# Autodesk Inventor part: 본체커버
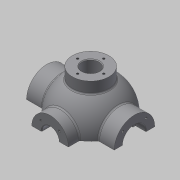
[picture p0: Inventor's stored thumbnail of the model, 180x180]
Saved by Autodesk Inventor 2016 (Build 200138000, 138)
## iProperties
Created: 2015-12
Part Number: 본체커버
Material: 일반
Document SubType Name: Modeling
Designer: mduedu
Density: 1 g/cm^3
Mass: 211.839 g
Surface Area: 451.737 cm^2
Volume: 211.839 cm^3
Appearance: 기본값
Author: mduedu
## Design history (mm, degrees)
sketch "스케치1"
  geometry: L1 (-53, 0)-(53, 0); A1 r 53 centre (0, 0) between (53, 0) and (-53, 0); 2 further points
  constraints: 2 coincident, 2 end point, 2 point on circle, 1 centre point, 1 horizontal, 1 midpoint
  dimensions: "d0" = 53 radius of A1
revolve "회전1" sketch "스케치1" stored, may be unused: angle "d2" = 90 deg
feature "쉘1" dims "d11" = 10
node "작업 평면1"
sketch "스케치2"
  geometry: C1 r 31 at (0, 0); 1 further point
  constraints: 1 centre point, 1 coincident
  dimensions: "d4" = 62 diameter of C1
extrude "돌출1" join sketch "스케치2" stored distance "d5" = 10; taper "d6" = 0 deg
node "작업 평면2"
sketch "스케치3"
  geometry: C1 r 28 at (0, 0); 1 further point
  constraints: 1 centre point, 1 coincident
  dimensions: "d8" = 56 diameter of C1
extrude "돌출2" join sketch "스케치3" stored distance "d9" = 10; taper "d10" = 0 deg
hole "구멍1" diameter "d14" = 35; stored, may be unused: countersink angle "d18" = 90 deg, drill point angle "d20" = 0 deg; dims "d12" = 10, "d13" = 10, "d15" = 6, "d16" = 4, "d17" = 2, "d19" = 16
hole "구멍2" diameter "d23" = 27; stored, may be unused: countersink angle "d27" = 90 deg, drill point angle "d29" = 0 deg; dims "d21" = 10, "d22" = 10, "d24" = 6, "d25" = 4, "d26" = 2, "d28" = 16
fillet "모깎기1" dims "d30" = 0.3
hole "구멍3" diameter "d33" = 26; stored, may be unused: countersink angle "d37" = 90 deg, drill point angle "d39" = 0 deg; dims "d31" = 10, "d32" = 10, "d34" = 6, "d35" = 4, "d36" = 2, "d38" = 16
chamfer "모따기1" distance "d40" = 1; stored, may be unused: second distance "d41" = 2, angle "d42" = 45 deg
sketch "스케치4"
  geometry: L1 (0, 0)-(0, -25); L2 (0, 0)-(-17.678, -17.678); A1 r 25 centre (0, 0) between (-17.678, -17.678) and (0, -25); 1 further point
  constraints: 4 end point, 2 point on circle, 1 centre point, 1 coincident, 1 vertical
  dimensions: "d43" = 50 diameter of A1; "d47" = 45 deg angle of L1 L2
hole "구멍4" sketch "스케치4" at (-17.678, -17.678) diameter "d49" = 3.242; stored, may be unused: countersink angle "d53" = 90 deg, drill point angle "d55" = 118 deg; dims "d50" = 11, "d51" = 4, "d52" = 2, "d54" = 13
sketch "스케치5"
  geometry: L1 (0, 0)-(0, -20); L2 (0, 0)-(-14.142, -14.142); A1 r 20 centre (0, 0) between (0, -20) and (-14.142, -14.142); 2 further points
  constraints: 4 end point, 2 coincident, 2 point on circle, 1 centre point, 1 vertical
  dimensions: "d59" = 40 diameter of A1; "d65" = 45 deg angle of L1 L2
hole "구멍5" sketch "스케치5" at (-14.142, -14.142) diameter "d67" = 3.242; stored, may be unused: countersink angle "d71" = 90 deg, drill point angle "d73" = 118 deg; dims "d68" = 8, "d69" = 4, "d70" = 2, "d72" = 10
node "작업 평면3"
sketch "스케치6"
  geometry: C1 r 65 at (0, 0); 1 further point
  constraints: 1 centre point, 1 coincident
  dimensions: "d78" = 130 diameter of C1
extrude "돌출3" join sketch "스케치6" distance "d80" = 10; taper "d81" = 0 deg
sketch "스케치7"
  geometry: C1 r 20 at (0, 0); 1 further point
  constraints: 1 centre point, 1 coincident
  dimensions: "d82" = 40 diameter of C1
extrude "돌출4" join sketch "스케치7" stored distance "d84" = 10; taper "d85" = 0 deg
sketch "스케치8"
  geometry: 2 further points
  constraints: 1 coincident
hole "구멍6" sketch "스케치8" at (0, 0) diameter "d86" = 20; stored, may be unused: countersink angle "d90" = 90 deg, drill point angle "d92" = 118 deg; dims "d87" = 7, "d88" = 40, "d89" = 5, "d91" = 10
fillet "모깎기2" dims "d93" = 0.3
sketch "스케치9"
  geometry: L1 (65, -75)-(-65, -75) reference; L2 (-45, -75)-(-38.245, -36.692); A1 r 53 centre (0, 0) between (42.988, 31) and (42.988, -31) reference; 1 further point
  constraints: 2 end point, 1 point on circle, 1 point on line
  dimensions: "d94" = 45 horizontal distance of L2.start point (0, 0); "d95" = 80 deg angle of L2 L1
feature "리브1" sketch "스케치9" dims "d96" = 1, "d97" = 8, "d98" = 0, "d99" = 0, "d100" = 1, "d101" = 1
sketch "스케치10"
  geometry: L1 (0, 0)-(0, -55); L2 (0, 0)-(-38.891, -38.891); A1 r 55 centre (0, 0) between (0, -55) and (-38.891, -38.891); 2 further points
  constraints: 4 end point, 2 coincident, 2 point on circle, 1 centre point, 1 vertical
  dimensions: "d105" = 110 diameter of A1; "d107" = 45 deg angle of L1 L2
hole "구멍7" sketch "스케치10" at (-38.891, -38.891) diameter "d109" = 10; stored, may be unused: countersink angle "d113" = 90 deg, drill point angle "d115" = 118 deg; dims "d110" = 7, "d111" = 40, "d112" = 5, "d114" = 10
fillet "모깎기3" dims "d120" = 3
fillet "모깎기4" dims "d121" = 3, "d122" = 3
fillet "모깎기5" dims "d123" = 3
fillet "모깎기6" dims "d124" = 3
sketch "스케치11"
  geometry: C1 r 5 at (-38.891, 38.891) reference; C2 r 5 at (38.891, 38.891) reference; C3 r 5 at (38.891, -38.891) reference; C4 r 5 at (-38.891, -38.891) reference; C5 r 20 at (0, 0) reference; C6 r 65 at (0, 0) reference; 1 further point
  constraints: 3 other
feature "엠보싱1" sketch "스케치11" dims "d125" = 0.5, "d126" = 0
sketch "스케치12"
  geometry: L1 (0, 100)-(0, -100); L2 (0, 100)-(-150, 100); L3 (-150, 100)-(-150, -100); L4 (-150, -100)-(0, -100); 2 further points
  constraints: 8 end point, 3 perpendicular, 1 coincident, 1 midpoint, 1 vertical
  dimensions: "d127" = 200 distance of L2.end L3.end; "d129" = 150 distance of L3.end L1.end
extrude "돌출5" cut sketch "스케치12" stored distance "d130" = 10; taper "d131" = 0 deg
sketch "스케치13"
  geometry: C1 r 7 at (0, -53); A1 r 53 centre (0, 0) between (-42.113, -32.179) and (42.113, -32.179) reference; 1 further point
  constraints: 1 centre point, 1 point on circle
  dimensions: "d132" = 14 diameter of C1
extrude "돌출6" join sketch "스케치13" distance "d133" = 5; taper "d134" = 0 deg
sketch "스케치14"
  geometry: C1 r 7 at (0, 0) reference; 1 further point
extrude "돌출7" cut sketch "스케치14" stored distance "d135" = 5; taper "d136" = 0 deg
sketch "스케치15"
  geometry: C1 r 2.25 at (0, 53); A1 r 7 centre (0, 53) between (6.965, 52.302) and (-6.965, 52.302) reference; 1 further point
  constraints: 1 centre point, 1 coincident
  dimensions: "d139" = 4.5 diameter of C1
extrude "돌출8" cut sketch "스케치15" stored distance "d141" = 5; taper "d142" = 0 deg
fillet "모깎기7" dims "d143" = 3
fillet "모깎기8" dims "d144" = 1
fillet "모깎기9" dims "d145" = 1
fillet "모깎기10" dims "d146" = 1
node "작업 평면4"
sketch "스케치16"
  geometry: C1 r 28 at (0, 0); 1 further point
  constraints: 1 centre point, 1 coincident
  dimensions: "d148" = 56 diameter of C1
extrude "돌출9" join sketch "스케치16" stored distance "d150" = 5; taper "d151" = 0 deg
hole "구멍8" diameter "d154" = 26; stored, may be unused: countersink angle "d158" = 90 deg, drill point angle "d160" = 118 deg; dims "d152" = 10, "d153" = 10, "d155" = 6, "d156" = 4, "d157" = 2, "d159" = 8
sketch "스케치17" dims "d161" = 40
  geometry: 3 further points
  constraints: 2 vertical alignment, 1 coincident, 2 other
hole "구멍9" sketch "스케치17" at (0, 20) diameter "d163" = 3.242; stored, may be unused: countersink angle "d167" = 90 deg, drill point angle "d169" = 118 deg; dims "d164" = 8, "d165" = 4, "d166" = 2, "d168" = 10
fillet "모깎기11" dims "d173" = 3
chamfer "모따기2" distance "d174" = 1; stored, may be unused: second distance "d175" = 2, angle "d176" = 45 deg
node "솔리드1"
mirror "대칭1"
mirror "대칭2"
pattern_circular "원형 패턴1" dims angle "d57" = 360 deg
mirror "대칭3"
pattern_circular "원형 패턴2" dims angle "d75" = 360 deg
pattern_circular "원형 패턴3" dims angle "d103" = 360 deg
pattern_circular "원형 패턴4" dims angle "d118" = 360 deg
pattern_circular "원형 패턴5" dims angle "d171" = 360 deg
node "투영된 루프1"
other parameters: "d3" = 67, "d7" = 62, "d77" = -85, "d147" = 62
